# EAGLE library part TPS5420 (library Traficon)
2A, wide input range, step-down swift converter
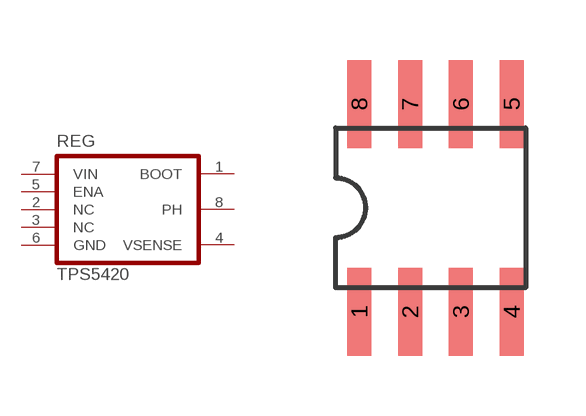
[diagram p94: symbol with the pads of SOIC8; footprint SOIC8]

Designator prefix REG

## TPS5420D  [SOIC8]
1  BOOT
2  NC
3  NC
4  VSENSE
5  ENA
6  GND
7  VIN
8  PH

## Footprint SOIC8 (pad centres in mm)
Small Outline IC
smd 0.6 x 2.2: 1 -1.905,-2.6; 2 -0.635,-2.6; 3 0.635,-2.6; 4 1.905,-2.6; 5 1.905,2.6; 6 0.635,2.6; 7 -0.635,2.6; 8 -1.905,2.6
